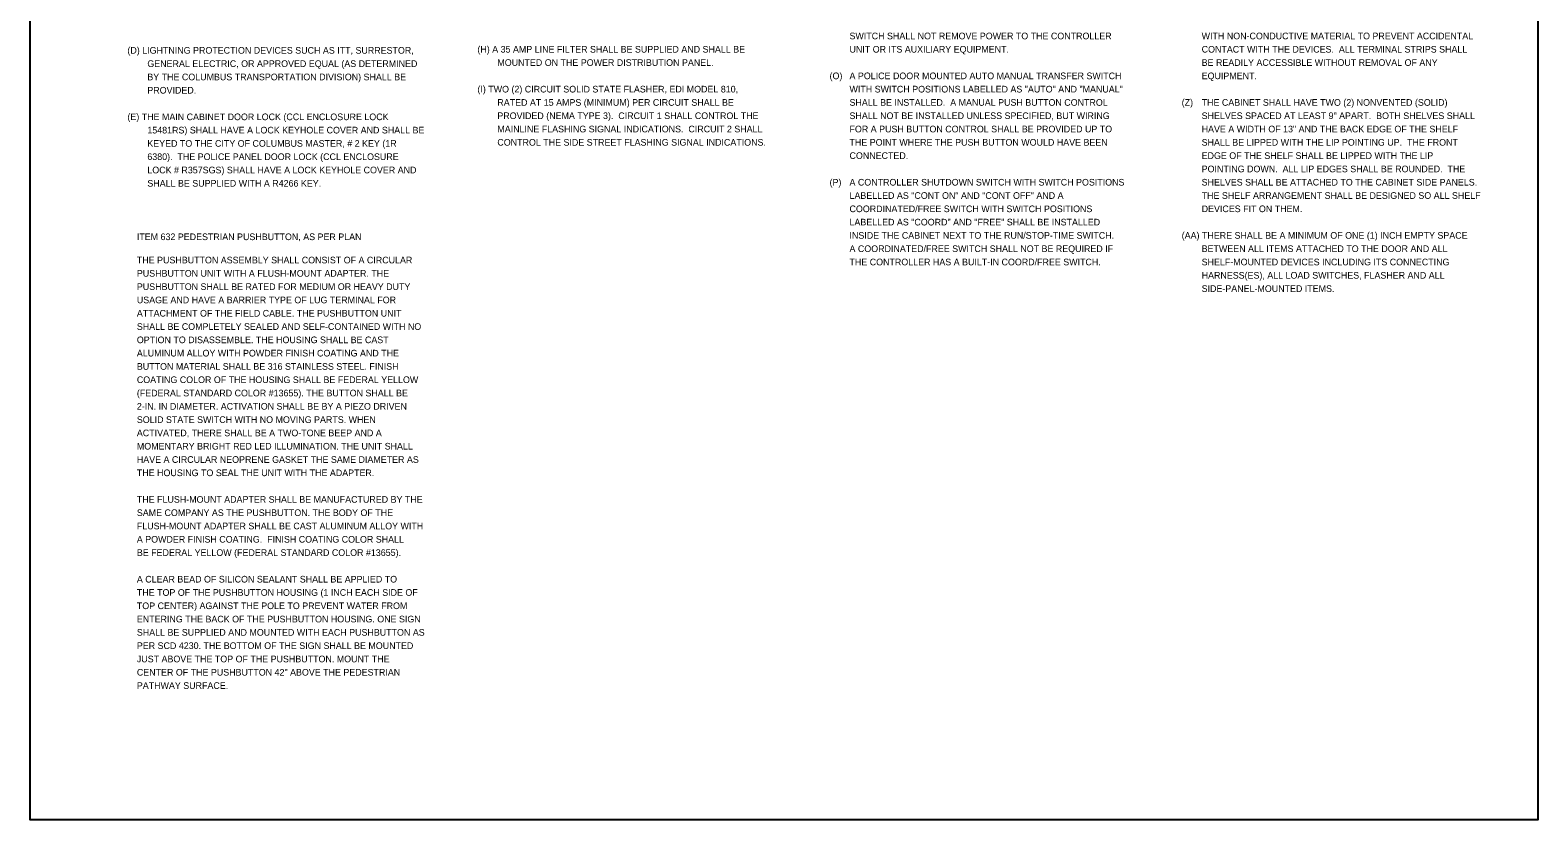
# Model space of a CAD drawing. Extents: x -27 to 74, y -37 to 38.
# Drawn here: x 42.58 to 74.35, y -36.62 to -19.99 of the extents above; entities that cross this region are included whole.
import ezdxf

# ---------------------------------------------------------------- set-up
doc = ezdxf.new("R2010")
doc.units = 0
doc.layers.add('SH_Data', color=7, linetype='Continuous')
doc.layers.add('SH_Text', color=7, linetype='Continuous')

msp = doc.modelspace()

# ---------------------------------------------------------------- linework, layer by layer
at = {"layer": 'SH_Text'}
msp.add_lwpolyline([(42.584, -3.293), (74.352, -3.293), (74.352, -36.623), (42.584, -36.623)], close=True, dxfattribs=at)

# ---------------------------------------------------------------- texts
at = {"layer": 'SH_Data'}
for s, p in [('(H) A 35 AMP LINE FILTER SHALL BE SUPPLIED AND SHALL BE ', (52.008, -20.467)), ('SWITCH SHALL NOT REMOVE POWER TO THE CONTROLLER ', (59.848, -20.187)), ('UNIT OR ITS AUXILIARY EQUIPMENT.', (59.848, -20.467)), ('WITH NON-CONDUCTIVE MATERIAL TO PREVENT ACCIDENTAL ', (67.268, -20.187)), ('CONTACT WITH THE DEVICES.  ALL TERMINAL STRIPS SHALL ', (67.268, -20.467)), ('(D) LIGHTNING PROTECTION DEVICES SUCH AS ITT, SURRESTOR, ', (44.633, -20.49)), ('GENERAL ELECTRIC, OR APPROVED EQUAL (AS DETERMINED ', (45.053, -20.77)), ('MOUNTED ON THE POWER DISTRIBUTION PANEL.', (52.428, -20.747)), ('BE READILY ACCESSIBLE WITHOUT REMOVAL OF ANY ', (67.268, -20.747)), ('BY THE COLUMBUS TRANSPORTATION DIVISION) SHALL BE ', (45.053, -21.05)), ('(O)', (59.428, -21.027)), ('A POLICE DOOR MOUNTED AUTO MANUAL TRANSFER SWITCH ', (59.848, -21.027)), ('EQUIPMENT.', (67.268, -21.027)), ('PROVIDED.', (45.053, -21.33)), ('(I) TWO (2) CIRCUIT SOLID STATE FLASHER, EDI MODEL 810, ', (52.008, -21.307)), ('WITH SWITCH POSITIONS LABELLED AS "AUTO" AND "MANUAL" ', (59.848, -21.307)), ('RATED AT 15 AMPS (MINIMUM) PER CIRCUIT SHALL BE ', (52.428, -21.587)), ('SHALL BE INSTALLED.  A MANUAL PUSH BUTTON CONTROL ', (59.848, -21.587)), ('(Z)', (66.848, -21.587)), ('THE CABINET SHALL HAVE TWO (2) NONVENTED (SOLID) ', (67.268, -21.587)), ('(E) THE MAIN CABINET DOOR LOCK (CCL ENCLOSURE LOCK ', (44.633, -21.89)), ('PROVIDED (NEMA TYPE 3).  CIRCUIT 1 SHALL CONTROL THE ', (52.428, -21.867)), ('SHALL NOT BE INSTALLED UNLESS SPECIFIED, BUT WIRING ', (59.848, -21.867)), ('SHELVES SPACED AT LEAST 9" APART.  BOTH SHELVES SHALL ', (67.268, -21.867)), ('15481RS) SHALL HAVE A LOCK KEYHOLE COVER AND SHALL BE ', (45.053, -22.17)), ('MAINLINE FLASHING SIGNAL INDICATIONS.  CIRCUIT 2 SHALL ', (52.428, -22.147)), ('FOR A PUSH BUTTON CONTROL SHALL BE PROVIDED UP TO ', (59.848, -22.147)), ('HAVE A WIDTH OF 13" AND THE BACK EDGE OF THE SHELF ', (67.268, -22.147)), ('KEYED TO THE CITY OF COLUMBUS MASTER, # 2 KEY (1R ', (45.053, -22.45)), ('CONTROL THE SIDE STREET FLASHING SIGNAL INDICATIONS.', (52.428, -22.427)), ('THE POINT WHERE THE PUSH BUTTON WOULD HAVE BEEN ', (59.848, -22.427)), ('SHALL BE LIPPED WITH THE LIP POINTING UP.  THE FRONT ', (67.268, -22.427)), ('6380).  THE POLICE PANEL DOOR LOCK (CCL ENCLOSURE ', (45.053, -22.73)), ('LOCK # R357SGS) SHALL HAVE A LOCK KEYHOLE COVER AND ', (45.053, -23.01)), ('CONNECTED.', (59.848, -22.707)), ('EDGE OF THE SHELF SHALL BE LIPPED WITH THE LIP ', (67.268, -22.707)), ('POINTING DOWN.  ALL LIP EDGES SHALL BE ROUNDED.  THE ', (67.268, -22.987)), ('SHALL BE SUPPLIED WITH A R4266 KEY. ', (45.053, -23.29)), ('(P)', (59.428, -23.267)), ('A CONTROLLER SHUTDOWN SWITCH WITH SWITCH POSITIONS ', (59.848, -23.267)), ('SHELVES SHALL BE ATTACHED TO THE CABINET SIDE PANELS.  ', (67.268, -23.267)), ('LABELLED AS "CONT ON" AND "CONT OFF" AND A ', (59.848, -23.547)), ('THE SHELF ARRANGEMENT SHALL BE DESIGNED SO ALL SHELF ', (67.268, -23.547)), ('COORDINATED/FREE SWITCH WITH SWITCH POSITIONS ', (59.848, -23.827)), ('DEVICES FIT ON THEM.', (67.268, -23.827)), ('LABELLED AS "COORD" AND "FREE" SHALL BE INSTALLED ', (59.848, -24.107)), ('ITEM 632 PEDESTRIAN PUSHBUTTON, AS PER PLAN', (44.832, -24.416)), ('INSIDE THE CABINET NEXT TO THE RUN/STOP-TIME SWITCH.  ', (59.848, -24.387)), ('(AA) THERE SHALL BE A MINIMUM OF ONE (1) INCH EMPTY SPACE ', (66.848, -24.387)), ('THE PUSHBUTTON ASSEMBLY SHALL CONSIST OF A CIRCULAR ', (44.832, -24.906)), ('A COORDINATED/FREE SWITCH SHALL NOT BE REQUIRED IF ', (59.848, -24.667)), ('BETWEEN ALL ITEMS ATTACHED TO THE DOOR AND ALL ', (67.268, -24.667)), ('PUSHBUTTON UNIT WITH A FLUSH-MOUNT ADAPTER. THE ', (44.832, -25.186)), ('THE CONTROLLER HAS A BUILT-IN COORD/FREE SWITCH.', (59.848, -24.947)), ('SHELF-MOUNTED DEVICES INCLUDING ITS CONNECTING ', (67.268, -24.947)), ('HARNESS(ES), ALL LOAD SWITCHES, FLASHER AND ALL ', (67.268, -25.227)), ('PUSHBUTTON SHALL BE RATED FOR MEDIUM OR HEAVY DUTY ', (44.832, -25.466)), ('SIDE-PANEL-MOUNTED ITEMS.', (67.268, -25.507)), ('USAGE AND HAVE A BARRIER TYPE OF LUG TERMINAL FOR ', (44.832, -25.746)), ('ATTACHMENT OF THE FIELD CABLE. THE PUSHBUTTON UNIT ', (44.832, -26.026)), ('SHALL BE COMPLETELY SEALED AND SELF-CONTAINED WITH NO ', (44.832, -26.306)), ('OPTION TO DISASSEMBLE. THE HOUSING SHALL BE CAST ', (44.832, -26.586)), ('ALUMINUM ALLOY WITH POWDER FINISH COATING AND THE ', (44.832, -26.866)), ('COATING COLOR OF THE HOUSING SHALL BE FEDERAL YELLOW ', (44.832, -27.426)), ('BUTTON MATERIAL SHALL BE 316 STAINLESS STEEL. FINISH ', (44.832, -27.146)), ('(FEDERAL STANDARD COLOR #13655). THE BUTTON SHALL BE ', (44.832, -27.706)), ('2-IN. IN DIAMETER. ACTIVATION SHALL BE BY A PIEZO DRIVEN ', (44.832, -27.986)), ('SOLID STATE SWITCH WITH NO MOVING PARTS. WHEN ', (44.832, -28.266)), ('ACTIVATED, THERE SHALL BE A TWO-TONE BEEP AND A ', (44.832, -28.546)), ('MOMENTARY BRIGHT RED LED ILLUMINATION. THE UNIT SHALL ', (44.832, -28.826)), ('HAVE A CIRCULAR NEOPRENE GASKET THE SAME DIAMETER AS ', (44.832, -29.106)), ('THE HOUSING TO SEAL THE UNIT WITH THE ADAPTER. ', (44.832, -29.386)), ('THE FLUSH-MOUNT ADAPTER SHALL BE MANUFACTURED BY THE ', (44.832, -29.946)), ('SAME COMPANY AS THE PUSHBUTTON. THE BODY OF THE ', (44.832, -30.226)), ('FLUSH-MOUNT ADAPTER SHALL BE CAST ALUMINUM ALLOY WITH ', (44.832, -30.506)), ('A POWDER FINISH COATING.  FINISH COATING COLOR SHALL ', (44.832, -30.786)), ('BE FEDERAL YELLOW (FEDERAL STANDARD COLOR #13655).', (44.832, -31.066)), ('A CLEAR BEAD OF SILICON SEALANT SHALL BE APPLIED TO ', (44.832, -31.626)), ('THE TOP OF THE PUSHBUTTON HOUSING (1 INCH EACH SIDE OF ', (44.832, -31.906)), ('TOP CENTER) AGAINST THE POLE TO PREVENT WATER FROM ', (44.832, -32.186)), ('ENTERING THE BACK OF THE PUSHBUTTON HOUSING. ONE SIGN ', (44.832, -32.466)), ('SHALL BE SUPPLIED AND MOUNTED WITH EACH PUSHBUTTON AS ', (44.832, -32.746)), ('PER SCD 4230. THE BOTTOM OF THE SIGN SHALL BE MOUNTED ', (44.832, -33.026)), ('JUST ABOVE THE TOP OF THE PUSHBUTTON. MOUNT THE ', (44.832, -33.306)), ('CENTER OF THE PUSHBUTTON 42" ABOVE THE PEDESTRIAN ', (44.832, -33.586)), ('PATHWAY SURFACE.  ', (44.832, -33.866))]:
    msp.add_text(s, height=0.14, dxfattribs=at).set_placement(p)

doc.saveas('drawing.dxf')
